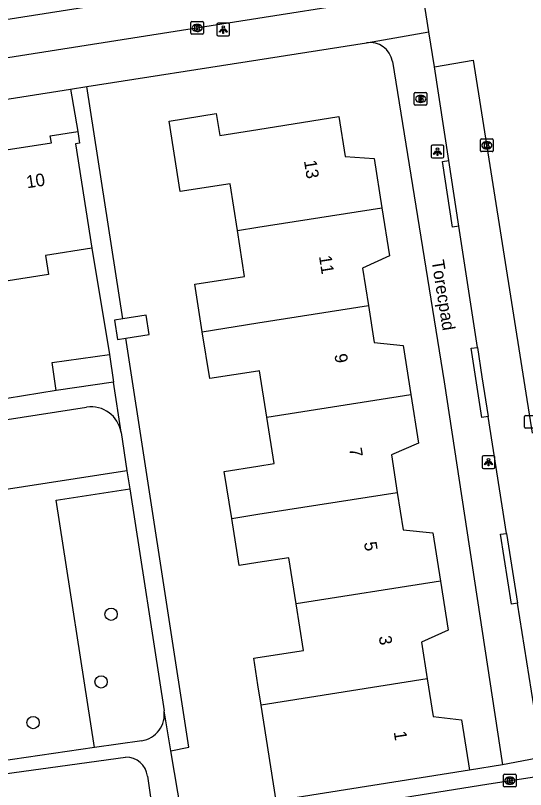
# Model space of a CAD drawing. Extents: x 160077 to 160945, y 386481 to 387498.
# Drawn here: x 160480.8 to 160521.2, y 387146.3 to 387207.7 of the extents above; entities that cross this region are included whole.
import ezdxf

# ---------------------------------------------------------------- set-up
doc = ezdxf.new("R2010")
doc.units = 0
for name, color, linetype in [('IMGEO_Boom', 7, 'Continuous'), ('IMGEO_Brandkraan', 7, 'Continuous'), ('IMGEO_Groenvoorziening', 7, 'Continuous'), ('IMGEO_Kolk', 7, 'Continuous'), ('IMGEO_Lichtpunt', 7, 'Continuous'), ('IMGEO_Openbare_ruimte_label', 7, 'Continuous'), ('IMGEO_Pand', 7, 'Continuous'), ('IMGEO_Pand_nummerreeks', 7, 'Continuous'), ('IMGEO_Rijbaan_lokaal_open', 7, 'Continuous'), ('IMGEO_Voetpad_open', 7, 'Continuous')]:
    doc.layers.add(name, color=color, linetype=linetype)

msp = doc.modelspace()

# ---------------------------------------------------------------- linework, layer by layer
at = {"layer": 'IMGEO_Boom'}
for centre in [(160488.357, 387160.227), (160487.568, 387154.866), (160482.178, 387151.64)]:
    msp.add_circle(centre, 0.489, dxfattribs=at)
at = {"layer": 'IMGEO_Brandkraan'}
for p, q in [((160512.397, 387200.653), (160512.397, 387201.505)), ((160512.472, 387201.579), (160513.324, 387201.579)), ((160512.885, 387201.359), (160512.91, 387201.359)), ((160513.398, 387201.505), (160513.398, 387200.653)), ((160513.324, 387200.579), (160512.472, 387200.579)), ((160512.908, 387200.799), (160512.883, 387200.799))]:
    msp.add_line(p, q, dxfattribs=at)
for points in [[(160512.397, 387200.653), (160512.397, 387201.505)], [(160512.472, 387201.579), (160513.324, 387201.579)], [(160512.745, 387201.279), (160512.745, 387200.879), (160512.958, 387200.879)], [(160512.976, 387201.279), (160512.745, 387201.279)], [(160512.924, 387201.198), (160512.87, 387201.198), (160512.87, 387201.122)], [(160512.87, 387201.122), (160512.923, 387201.122)], [(160513.398, 387201.505), (160513.398, 387200.653)], [(160513.324, 387200.579), (160512.472, 387200.579)], [(160512.932, 387201.046), (160512.87, 387201.046), (160512.87, 387200.965)], [(160512.87, 387200.965), (160512.932, 387200.965)]]:
    msp.add_lwpolyline(points, dxfattribs=at)
for centre, radius, start, end in [((160512.474, 387201.503), 0.0765, 91.55205, 178.44795), ((160512.474, 387201.503), 0.0765, 91.55205, 178.44795), ((160512.925, 387201.16), 0.0379, 267.82845, 90.93552), ((160512.98, 387201.134), 0.145, 59.4692, 91.53667), ((160513.005, 387201.181), 0.0922, 285.51372, 58.15012), ((160513.01, 387200.989), 0.105, 301.31148, 78.98903), ((160513.322, 387201.503), 0.0765, 1.55205, 88.44795), ((160513.322, 387201.503), 0.0765, 1.55205, 88.44795), ((160512.474, 387200.655), 0.0765, 181.55205, 268.44795), ((160512.474, 387200.655), 0.0765, 181.55205, 268.44795), ((160512.933, 387201.005), 0.0404, 269.87594, 90.50774), ((160512.964, 387201.13), 0.251, 268.66757, 293.53466), ((160513.322, 387200.655), 0.0765, 271.55205, 358.44795), ((160513.322, 387200.655), 0.0765, 271.55205, 358.44795)]:
    msp.add_arc(centre, radius, start, end, dxfattribs=at)
for centre, major_axis, ratio, start_param, end_param in [((160512.884, 387201.079), (-0.387, 0.002), 0.722429, 4.712389, 7.853982), ((160512.909, 387201.079), (-0.39, 0.002), 0.717154, 1.570796, 4.712389)]:
    msp.add_ellipse(centre, major_axis=major_axis, ratio=ratio, start_param=start_param, end_param=end_param, dxfattribs=at)
at = {"layer": 'IMGEO_Groenvoorziening'}
for points in [[(160498.218, 387210.216), (160471.06, 387205.939)], [(160489.619, 387171.598), (160454.256, 387166.131)], [(160487.035, 387149.659), (160484.013, 387169.274), (160489.839, 387170.175)]]:
    msp.add_lwpolyline(points, dxfattribs=at)
at = {"layer": 'IMGEO_Kolk'}
for p, q in [((160494.688, 387206.279), (160494.688, 387207.131)), ((160494.763, 387207.205), (160495.615, 387207.205)), ((160495.176, 387206.985), (160495.201, 387206.985)), ((160495.689, 387207.131), (160495.689, 387206.279)), ((160495.615, 387206.205), (160494.763, 387206.205)), ((160495.199, 387206.425), (160495.174, 387206.425)), ((160517.646, 387196.975), (160517.646, 387197.827)), ((160517.721, 387197.901), (160518.573, 387197.901)), ((160518.134, 387197.681), (160518.159, 387197.681)), ((160518.647, 387197.827), (160518.647, 387196.975)), ((160518.573, 387196.901), (160517.721, 387196.901)), ((160518.157, 387197.121), (160518.132, 387197.121)), ((160521.215, 387175.983), (160522.067, 387175.983)), ((160521.14, 387175.057), (160521.14, 387175.909)), ((160522.067, 387174.983), (160521.215, 387174.983)), ((160519.472, 387146.616), (160519.472, 387147.468)), ((160519.547, 387147.542), (160520.399, 387147.542)), ((160519.96, 387147.322), (160519.985, 387147.322)), ((160520.473, 387147.468), (160520.473, 387146.616)), ((160520.399, 387146.542), (160519.547, 387146.542)), ((160519.983, 387146.762), (160519.958, 387146.762))]:
    msp.add_line(p, q, dxfattribs=at)
for points in [[(160494.688, 387206.279), (160494.688, 387207.131)], [(160494.763, 387207.205), (160495.615, 387207.205)], [(160495.009, 387206.905), (160495.132, 387206.905), (160495.132, 387206.754), (160495.262, 387206.905), (160495.426, 387206.905), (160495.28, 387206.754), (160495.433, 387206.505), (160495.281, 387206.505), (160495.196, 387206.669), (160495.132, 387206.602), (160495.132, 387206.505), (160495.009, 387206.505), (160495.009, 387206.905)], [(160495.689, 387207.131), (160495.689, 387206.279)], [(160495.615, 387206.205), (160494.763, 387206.205)], [(160517.646, 387196.975), (160517.646, 387197.827)], [(160517.721, 387197.901), (160518.573, 387197.901)], [(160517.967, 387197.601), (160518.09, 387197.601), (160518.09, 387197.45), (160518.22, 387197.601), (160518.384, 387197.601), (160518.238, 387197.45), (160518.391, 387197.201), (160518.239, 387197.201), (160518.154, 387197.365), (160518.09, 387197.298), (160518.09, 387197.201), (160517.967, 387197.201), (160517.967, 387197.601)], [(160518.647, 387197.827), (160518.647, 387196.975)], [(160518.573, 387196.901), (160517.721, 387196.901)], [(160521.215, 387175.983), (160522.067, 387175.983)], [(160521.14, 387175.057), (160521.14, 387175.909)], [(160522.067, 387174.983), (160521.215, 387174.983)], [(160519.472, 387146.616), (160519.472, 387147.468)], [(160519.547, 387147.542), (160520.399, 387147.542)], [(160519.793, 387147.242), (160519.916, 387147.242), (160519.916, 387147.091), (160520.046, 387147.242), (160520.21, 387147.242), (160520.064, 387147.091), (160520.217, 387146.842), (160520.065, 387146.842), (160519.98, 387147.006), (160519.916, 387146.939), (160519.916, 387146.842), (160519.793, 387146.842), (160519.793, 387147.242)], [(160520.473, 387147.468), (160520.473, 387146.616)], [(160520.399, 387146.542), (160519.547, 387146.542)]]:
    msp.add_lwpolyline(points, dxfattribs=at)
for centre, start, end in [((160494.765, 387207.129), 91.55205, 178.44795), ((160494.765, 387207.129), 91.55205, 178.44795), ((160495.613, 387207.129), 1.55205, 88.44795), ((160495.613, 387207.129), 1.55205, 88.44795), ((160494.765, 387206.281), 181.55205, 268.44795), ((160494.765, 387206.281), 181.55205, 268.44795), ((160495.613, 387206.281), 271.55205, 358.44795), ((160495.613, 387206.281), 271.55205, 358.44795), ((160517.723, 387197.825), 91.55205, 178.44795), ((160517.723, 387197.825), 91.55205, 178.44795), ((160518.571, 387197.825), 1.55205, 88.44795), ((160518.571, 387197.825), 1.55205, 88.44795), ((160517.723, 387196.977), 181.55205, 268.44795), ((160517.723, 387196.977), 181.55205, 268.44795), ((160518.571, 387196.977), 271.55205, 358.44795), ((160518.571, 387196.977), 271.55205, 358.44795), ((160521.217, 387175.907), 91.55205, 178.44795), ((160521.217, 387175.907), 91.55205, 178.44795), ((160521.217, 387175.059), 181.55205, 268.44795), ((160521.217, 387175.059), 181.55205, 268.44795), ((160519.549, 387147.466), 91.55205, 178.44795), ((160519.549, 387147.466), 91.55205, 178.44795), ((160520.397, 387147.466), 1.55205, 88.44795), ((160520.397, 387147.466), 1.55205, 88.44795), ((160519.549, 387146.618), 181.55205, 268.44795), ((160519.549, 387146.618), 181.55205, 268.44795), ((160520.397, 387146.618), 271.55205, 358.44795), ((160520.397, 387146.618), 271.55205, 358.44795)]:
    msp.add_arc(centre, 0.0765, start, end, dxfattribs=at)
for centre, major_axis, ratio, start_param, end_param in [((160495.175, 387206.705), (-0.387, 0.002), 0.722429, 4.712389, 7.853982), ((160495.2, 387206.705), (-0.39, 0.002), 0.717154, 1.570796, 4.712389), ((160518.133, 387197.401), (-0.387, 0.002), 0.722429, 4.712389, 7.853982), ((160518.158, 387197.401), (-0.39, 0.002), 0.717154, 1.570796, 4.712389), ((160519.959, 387147.042), (-0.387, 0.002), 0.722429, 4.712389, 7.853982), ((160519.984, 387147.042), (-0.39, 0.002), 0.717154, 1.570796, 4.712389)]:
    msp.add_ellipse(centre, major_axis=major_axis, ratio=ratio, start_param=start_param, end_param=end_param, dxfattribs=at)
at = {"layer": 'IMGEO_Lichtpunt'}
for p, q in [((160496.753, 387206.982), (160496.753, 387206.175)), ((160496.753, 387206.982), (160496.753, 387206.175)), ((160497.655, 387207.077), (160496.847, 387207.077)), ((160497.655, 387207.077), (160496.847, 387207.077)), ((160497.749, 387206.175), (160497.749, 387206.982)), ((160497.749, 387206.175), (160497.749, 387206.982)), ((160496.847, 387206.081), (160497.655, 387206.081)), ((160496.847, 387206.081), (160497.655, 387206.081)), ((160514.636, 387197.402), (160513.828, 387197.402)), ((160514.636, 387197.402), (160513.828, 387197.402)), ((160513.734, 387197.307), (160513.734, 387196.5)), ((160513.734, 387197.307), (160513.734, 387196.5)), ((160514.73, 387196.5), (160514.73, 387197.307)), ((160514.73, 387196.5), (160514.73, 387197.307)), ((160513.828, 387196.406), (160514.636, 387196.406)), ((160513.828, 387196.406), (160514.636, 387196.406)), ((160517.78, 387172.691), (160517.78, 387171.884)), ((160517.78, 387172.691), (160517.78, 387171.884)), ((160518.682, 387172.786), (160517.874, 387172.786)), ((160518.682, 387172.786), (160517.874, 387172.786)), ((160518.776, 387171.884), (160518.776, 387172.691)), ((160518.776, 387171.884), (160518.776, 387172.691)), ((160517.874, 387171.79), (160518.682, 387171.79)), ((160517.874, 387171.79), (160518.682, 387171.79))]:
    msp.add_line(p, q, dxfattribs=at)
for points in [[(160497.127, 387206.646), (160497.166, 387206.618), (160496.978, 387206.356), (160496.94, 387206.383), (160497.127, 387206.646)], [(160497.339, 387206.618), (160497.377, 387206.645), (160497.564, 387206.383), (160497.525, 387206.355), (160497.339, 387206.618)], [(160497.229, 387206.598), (160497.276, 387206.598), (160497.276, 387206.276), (160497.229, 387206.276), (160497.229, 387206.598)], [(160514.108, 387196.971), (160514.147, 387196.943), (160513.959, 387196.681), (160513.921, 387196.708), (160514.108, 387196.971)], [(160514.21, 387196.923), (160514.257, 387196.923), (160514.257, 387196.601), (160514.21, 387196.601), (160514.21, 387196.923)], [(160514.32, 387196.943), (160514.358, 387196.97), (160514.545, 387196.708), (160514.506, 387196.68), (160514.32, 387196.943)], [(160518.154, 387172.355), (160518.193, 387172.327), (160518.005, 387172.065), (160517.967, 387172.092), (160518.154, 387172.355)], [(160518.256, 387172.307), (160518.303, 387172.307), (160518.303, 387171.985), (160518.256, 387171.985), (160518.256, 387172.307)], [(160518.366, 387172.327), (160518.404, 387172.354), (160518.591, 387172.092), (160518.552, 387172.064), (160518.366, 387172.327)]]:
    msp.add_lwpolyline(points, dxfattribs=at)
for centre in [(160497.252, 387206.78), (160514.233, 387197.105), (160518.279, 387172.489)]:
    msp.add_circle(centre, 0.0994, dxfattribs=at)
for centre, start, end in [((160496.847, 387206.982), 90, 180), ((160496.847, 387206.982), 90, 180), ((160497.655, 387206.982), 0, 90), ((160497.655, 387206.982), 0, 90), ((160496.847, 387206.175), 180, 270), ((160496.847, 387206.175), 180, 270), ((160497.655, 387206.175), 270, 0), ((160497.655, 387206.175), 270, 360), ((160513.828, 387197.307), 90, 180), ((160513.828, 387197.307), 90, 180), ((160514.636, 387197.307), 0, 90), ((160514.636, 387197.307), 0, 90), ((160513.828, 387196.5), 180, 270), ((160513.828, 387196.5), 180, 270), ((160514.636, 387196.5), 270, 0), ((160514.636, 387196.5), 270, 360), ((160517.874, 387172.691), 90, 180), ((160517.874, 387172.691), 90, 180), ((160518.682, 387172.691), 0, 90), ((160518.682, 387172.691), 0, 90), ((160517.874, 387171.884), 180, 270), ((160517.874, 387171.884), 180, 270), ((160518.682, 387171.884), 270, 0), ((160518.682, 387171.884), 270, 360)]:
    msp.add_arc(centre, 0.0946, start, end, dxfattribs=at)
at = {"layer": 'IMGEO_Pand'}
for points in [[(160498.375, 387190.643), (160497.79, 387194.354), (160493.838, 387193.731), (160492.957, 387199.323), (160496.699, 387199.913), (160496.971, 387198.184), (160500, 387198.661), (160506.414, 387199.672), (160506.913, 387196.508), (160509.219, 387196.349), (160509.834, 387192.446)], [(160478.284, 387196.768), (160483.623, 387197.605), (160483.535, 387198.16), (160485.72, 387198.503)], [(160485.72, 387198.503), (160485.865, 387197.582), (160485.53, 387197.53), (160486.83, 387189.238)], [(160498.375, 387190.643), (160500, 387190.899), (160509.834, 387192.446)], [(160509.834, 387192.446), (160510.436, 387188.629), (160508.296, 387187.663), (160508.764, 387184.695)], [(160495.589, 387182.623), (160494.995, 387186.391), (160498.947, 387187.014), (160498.375, 387190.643)], [(160486.83, 387189.238), (160483.167, 387188.662), (160483.402, 387187.16), (160479.868, 387186.605)], [(160495.589, 387182.623), (160500, 387183.317), (160508.764, 387184.695)], [(160508.764, 387184.695), (160509.225, 387181.771), (160511.51, 387181.522), (160512.122, 387177.642)], [(160489.521, 387182.103), (160491.379, 387182.403), (160491.133, 387183.927), (160489.284, 387183.636)], [(160489.284, 387183.636), (160488.628, 387183.533), (160488.87, 387181.998), (160489.521, 387182.103)], [(160500.707, 387175.846), (160500.127, 387179.527), (160500, 387179.507), (160496.176, 387178.904), (160495.589, 387182.623)], [(160484.002, 387177.964), (160483.685, 387180.175), (160488.237, 387180.828)], [(160488.237, 387180.828), (160488.554, 387178.617)], [(160488.554, 387178.617), (160484.002, 387177.964)], [(160500.707, 387175.846), (160512.122, 387177.642)], [(160512.122, 387177.642), (160512.731, 387173.778), (160510.578, 387172.854), (160511.045, 387169.889)], [(160497.922, 387167.825), (160497.336, 387171.545), (160500, 387171.966), (160501.287, 387172.168), (160500.707, 387175.846)], [(160497.922, 387167.825), (160500, 387168.152), (160511.045, 387169.889)], [(160511.045, 387169.889), (160511.511, 387166.931), (160513.875, 387166.675), (160514.479, 387162.847)], [(160503.04, 387161.048), (160502.463, 387164.71), (160500, 387164.322), (160498.511, 387164.087), (160497.922, 387167.825)], [(160514.479, 387162.847), (160503.04, 387161.048)], [(160514.479, 387162.847), (160515.092, 387158.957), (160512.958, 387158.03), (160513.42, 387155.099)], [(160500.254, 387153.028), (160500, 387154.643), (160499.67, 387156.738), (160500, 387156.79), (160503.621, 387157.361), (160503.04, 387161.048)], [(160513.42, 387155.099), (160500.254, 387153.028)], [(160513.42, 387155.099), (160513.89, 387152.114), (160516.136, 387151.87), (160516.768, 387147.865)], [(160501.448, 387145.45), (160500.254, 387153.028)], [(160516.768, 387147.865), (160501.448, 387145.45)]]:
    msp.add_lwpolyline(points, dxfattribs=at)
at = {"layer": 'IMGEO_Rijbaan_lokaal_open'}
for points in [[(160513.988, 387203.613), (160517.066, 387204.154), (160521.734, 387174.596)], [(160515.125, 387196.205), (160513.988, 387203.613)], [(160515.927, 387190.987), (160515.125, 387196.205)], [(160517.401, 387181.386), (160515.927, 387190.987)], [(160517.401, 387181.386), (160517.762, 387179.037), (160518.256, 387175.902)], [(160519.716, 387166.643), (160518.256, 387175.902)], [(160519.716, 387166.643), (160520.588, 387161.109)], [(160522.053, 387151.816), (160520.588, 387161.109)], [(160493.782, 387142.868), (160500, 387143.854), (160518.297, 387146.776), (160522.624, 387147.455)]]:
    msp.add_lwpolyline(points, dxfattribs=at)
at = {"layer": 'IMGEO_Voetpad_open'}
for points in [[(160513.55, 387206.404), (160508.282, 387239.959)], [(160507.733, 387208.672), (160500, 387207.46), (160451.075, 387199.755)], [(160508.597, 387205.531), (160513.55, 387206.404)], [(160513.988, 387203.613), (160513.553, 387206.385), (160513.55, 387206.404)], [(160486.443, 387202.053), (160500, 387204.183), (160508.597, 387205.531)], [(160510.656, 387204.038), (160514.764, 387178.646), (160519.378, 387148.285)], [(160451.238, 387196.523), (160485.133, 387201.848)], [(160485.133, 387201.848), (160486.443, 387202.053)], [(160485.133, 387201.848), (160485.72, 387198.503)], [(160489.284, 387183.636), (160486.443, 387202.053)], [(160515.927, 387190.987), (160515.433, 387190.912), (160514.631, 387196.13), (160515.125, 387196.205)], [(160486.83, 387189.238), (160488.237, 387180.828)], [(160493.093, 387149.407), (160494.522, 387149.687), (160489.521, 387182.103)], [(160518.256, 387175.902), (160517.762, 387175.827), (160516.907, 387181.311), (160517.401, 387181.386)], [(160489.149, 387174.646), (160489.155, 387174.657), (160488.554, 387178.617)], [(160484.002, 387177.964), (160478.8, 387177.121)], [(160454.256, 387166.131), (160453.401, 387171.506), (160486.417, 387176.643)], [(160489.149, 387174.646), (160489.619, 387171.598)], [(160489.619, 387171.598), (160489.839, 387170.175)], [(160489.839, 387170.175), (160492.554, 387152.587)], [(160520.588, 387161.109), (160520.095, 387161.032), (160519.223, 387166.566), (160519.716, 387166.643)], [(160493.093, 387149.407), (160492.562, 387152.579), (160492.554, 387152.587)], [(160490.79, 387150.207), (160487.035, 387149.659)], [(160487.035, 387149.659), (160476.173, 387148.072), (160459.449, 387145.885)], [(160501.448, 387145.45), (160500, 387145.329), (160493.933, 387144.411), (160493.093, 387149.407)], [(160463.394, 387145.308), (160489.513, 387148.892)], [(160522.023, 387148.799), (160519.378, 387148.285)], [(160519.378, 387148.285), (160516.768, 387147.865)], [(160491.247, 387147.408), (160491.654, 387144.624)]]:
    msp.add_lwpolyline(points, dxfattribs=at)
for centre, radius, start, end in [((160508.878, 387203.752), 1.801, 9.14398, 98.96359), ((160486.776, 387174.267), 2.403, 9.07783, 98.59107), ((160490.489, 387152.274), 2.088, 278.27907, 8.63099), ((160489.578, 387147.213), 1.68, 6.66493, 92.21961)]:
    msp.add_arc(centre, radius, start, end, dxfattribs=at)

# ---------------------------------------------------------------- texts
at = {"layer": 'IMGEO_Openbare_ruimte_label'}
msp.add_text('Torecpad', height=1, rotation=279.20797, dxfattribs=at).set_placement((160513.756, 387188.235))
at = {"layer": 'IMGEO_Pand_nummerreeks'}
for s, rotation, p in [('13', 278.93533, (160503.645, 387196.165)), ('10', 8.84994, (160481.711, 387193.99)), ('11', 278.93533, (160504.834, 387188.602)), ('9', 278.93533, (160506.058, 387180.811)), ('7', 278.93533, (160507.23, 387173.361)), ('5', 278.93533, (160508.401, 387165.912)), ('3', 278.93533, (160509.572, 387158.462)), ('1', 278.93533, (160510.761, 387150.901))]:
    msp.add_text(s, height=1, rotation=rotation, dxfattribs=at).set_placement(p)

doc.saveas('drawing.dxf')
